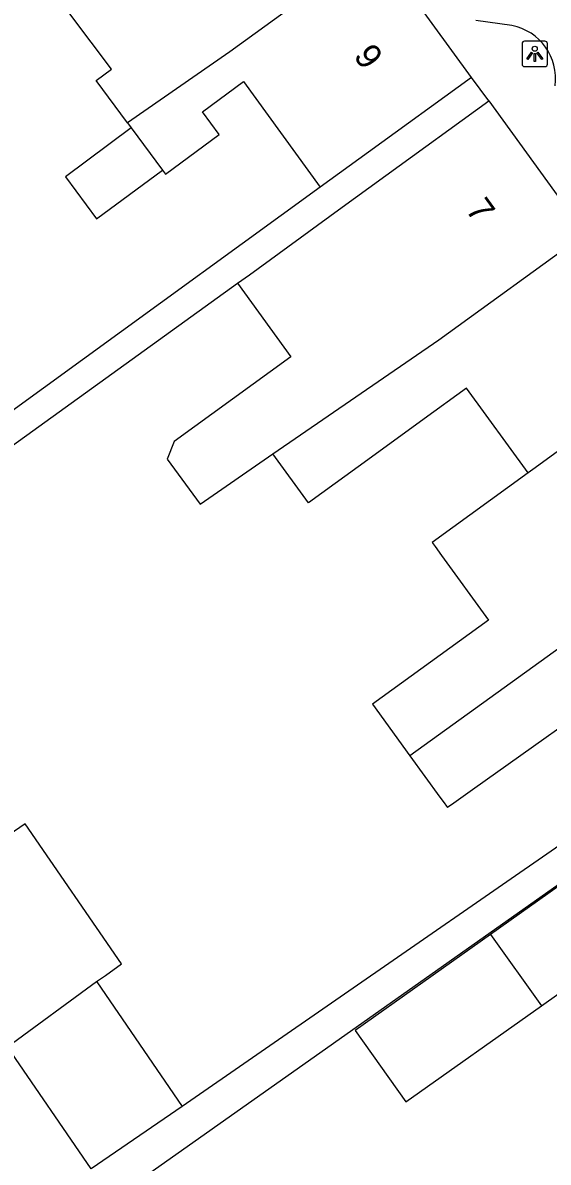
# Model space of a CAD drawing. Extents: x 161882 to 162509, y 381687 to 382379.
# Drawn here: x 162171.9 to 162192.56, y 381897.93 to 381942.76 of the extents above; entities that cross this region are included whole.
import ezdxf

# ---------------------------------------------------------------- set-up
doc = ezdxf.new("R2010")
doc.units = 0
for name, color, linetype in [('IMGEO_Lichtpunt', 7, 'Continuous'), ('IMGEO_Pand', 7, 'Continuous'), ('IMGEO_Pand_nummerreeks', 7, 'Continuous'), ('IMGEO_Rijbaan_lokaal_open', 7, 'Continuous'), ('IMGEO_Voetpad_open', 7, 'Continuous')]:
    doc.layers.add(name, color=color, linetype=linetype)

msp = doc.modelspace()

# ---------------------------------------------------------------- linework, layer by layer
at = {"layer": 'IMGEO_Lichtpunt'}
for p, q in [((162191.531, 381941.935), (162191.531, 381941.128)), ((162191.531, 381941.935), (162191.531, 381941.128)), ((162192.433, 381942.03), (162191.625, 381942.03)), ((162192.433, 381942.03), (162191.625, 381942.03)), ((162192.527, 381941.128), (162192.527, 381941.935)), ((162192.527, 381941.128), (162192.527, 381941.935)), ((162191.625, 381941.034), (162192.433, 381941.034)), ((162191.625, 381941.034), (162192.433, 381941.034))]:
    msp.add_line(p, q, dxfattribs=at)
for points in [[(162191.905, 381941.599), (162191.944, 381941.571), (162191.756, 381941.309), (162191.718, 381941.336), (162191.905, 381941.599)], [(162192.007, 381941.551), (162192.054, 381941.551), (162192.054, 381941.229), (162192.007, 381941.229), (162192.007, 381941.551)], [(162192.117, 381941.571), (162192.155, 381941.598), (162192.342, 381941.336), (162192.303, 381941.308), (162192.117, 381941.571)]]:
    msp.add_lwpolyline(points, dxfattribs=at)
msp.add_circle((162192.03, 381941.733), 0.0994, dxfattribs=at)
for centre, start, end in [((162191.625, 381941.935), 90, 180), ((162191.625, 381941.935), 90, 180), ((162192.433, 381941.935), 0, 90), ((162192.433, 381941.935), 0, 90), ((162191.625, 381941.128), 180, 270), ((162191.625, 381941.128), 180, 270), ((162192.433, 381941.128), 270, 0), ((162192.433, 381941.128), 270, 360)]:
    msp.add_arc(centre, 0.0946, start, end, dxfattribs=at)
at = {"layer": 'IMGEO_Pand'}
for points in [[(162185.784, 381945.777), (162180.044, 381941.612), (162176.016, 381938.823)], [(162189.54, 381940.599), (162185.784, 381945.777)], [(162176.016, 381938.823), (162174.783, 381940.488), (162175.389, 381940.937), (162172.942, 381944.178)], [(162189.54, 381940.599), (162185.493, 381937.664), (162183.594, 381936.286)], [(162177.393, 381936.963), (162177.512, 381936.802), (162179.617, 381938.361), (162178.961, 381939.247), (162180.577, 381940.444), (162183.594, 381936.286)], [(162180.345, 381932.509), (162180.807, 381932.845), (162184.317, 381935.392), (162186.18, 381936.744), (162190.227, 381939.679)], [(162190.227, 381939.679), (162194.014, 381934.46)], [(162176.016, 381938.823), (162176.166, 381938.62)], [(162176.166, 381938.62), (162173.573, 381936.7), (162174.8, 381935.043), (162177.393, 381936.963)], [(162176.166, 381938.62), (162177.393, 381936.963)], [(162181.737, 381925.793), (162188.26, 381930.286), (162194.014, 381934.46)], [(162180.345, 381932.509), (162182.442, 381929.619), (162177.857, 381926.29), (162177.579, 381925.594), (162178.868, 381923.817), (162181.737, 381925.793)], [(162197.713, 381929.361), (162191.96, 381925.187), (162191.766, 381925.054)], [(162191.766, 381925.054), (162189.346, 381928.389), (162187.681, 381927.18), (162185.605, 381925.674), (162183.128, 381923.877), (162181.737, 381925.793)], [(162191.766, 381925.054), (162187.995, 381922.31), (162188.111, 381922.15), (162188.367, 381921.798), (162190.206, 381919.262), (162185.646, 381915.954), (162187.121, 381913.922)], [(162201.412, 381924.261), (162195.66, 381920.088), (162187.121, 381913.922)], [(162187.121, 381913.922), (162188.303, 381912.292), (162188.43, 381912.117), (162188.593, 381911.892), (162188.641, 381911.926), (162188.844, 381912.071), (162189.576, 381912.591), (162195.779, 381916.999), (162196.043, 381916.635), (162197.223, 381917.474), (162199.228, 381914.711)], [(162174.803, 381905.04), (162175.156, 381905.282), (162175.78, 381905.732), (162171.997, 381911.251), (162170.299, 381910.087)], [(162192.29, 381904.086), (162197.286, 381907.633), (162195.291, 381910.443), (162190.296, 381906.895)], [(162190.296, 381906.895), (162184.97, 381903.114), (162186.965, 381900.305), (162192.29, 381904.086)], [(162190.296, 381906.895), (162192.29, 381904.086)], [(162171.292, 381902.474), (162174.803, 381905.04)], [(162174.803, 381905.04), (162174.809, 381905.031), (162178.17, 381900.128)], [(162178.17, 381900.128), (162174.585, 381897.67), (162171.292, 381902.474)]]:
    msp.add_lwpolyline(points, dxfattribs=at)
at = {"layer": 'IMGEO_Rijbaan_lokaal_open'}
msp.add_lwpolyline([(162191.13, 381942.643), (162189.716, 381942.842)], dxfattribs=at)
msp.add_arc((162190.741, 381940.572), 2.107, 351.8755, 79.3553, dxfattribs=at)
at = {"layer": 'IMGEO_Voetpad_open'}
for points in [[(162190.227, 381939.679), (162189.54, 381940.599)], [(162183.594, 381936.286), (162164.885, 381922.71)], [(162163.663, 381920.492), (162180.345, 381932.509)], [(162199.228, 381914.711), (162178.17, 381900.128)], [(162181.899, 381886.04), (162174.798, 381896.036), (162197.982, 381912.41)]]:
    msp.add_lwpolyline(points, dxfattribs=at)

# ---------------------------------------------------------------- texts
at = {"layer": 'IMGEO_Pand_nummerreeks'}
for s, p in [('9', (162184.876, 381941.444)), ('7', (162189.283, 381935.396))]:
    msp.add_text(s, height=1, rotation=305.9586, dxfattribs=at).set_placement(p)

doc.saveas('drawing.dxf')
